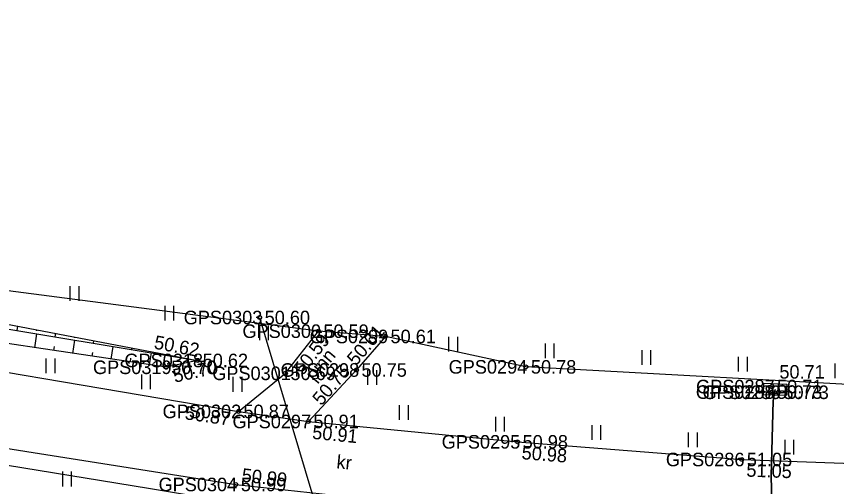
# Model space of a CAD drawing. Extents: x 551623 to 559850, y 6561220 to 6567135.
# Drawn here: x 555747.99 to 555790.35, y 6565368.67 to 6565392.98 of the extents above; entities that cross this region are included whole.
import ezdxf

# ---------------------------------------------------------------- set-up
doc = ezdxf.new("R2010")
doc.units = 0
for name, color, linetype in [('ELRAJATISMP', 7, 'Continuous'), ('HALJASTUS', 7, 'Continuous'), ('KORGUS-EH2000', 7, 'Continuous'), ('KPOHULIIN', 7, 'Continuous'), ('MOOTKORG-EH2000', 7, 'Continuous'), ('MOOTMPUNKT', 7, 'Continuous'), ('MOOTNR', 7, 'Continuous'), ('MOOTPIIR', 7, 'Continuous'), ('MPKAABEL', 7, 'Continuous'), ('RELJEEF', 7, 'Continuous'), ('TEE', 7, 'Continuous')]:
    doc.layers.add(name, color=color, linetype=linetype)

msp = doc.modelspace()

# ---------------------------------------------------------------- linework, layer by layer
at = {"layer": 'ELRAJATISMP'}
for p, q in [((555787.054, 6565373.996), (555787.035, 6565373.4)), ((555787.325, 6565373.988), (555787.306, 6565373.391))]:
    msp.add_line(p, q, dxfattribs=at)
msp.add_lwpolyline([(555786.593, 6565374.011), (555787.787, 6565373.973), (555787.768, 6565373.376), (555786.574, 6565373.414)], close=True, dxfattribs=at)
at = {"layer": 'HALJASTUS'}
for p, q in [((555750.751, 6565379.034), (555750.751, 6565378.273)), ((555751.206, 6565379.034), (555751.206, 6565378.273)), ((555755.647, 6565378.018), (555755.647, 6565377.257)), ((555756.102, 6565378.018), (555756.102, 6565377.257)), ((555760.542, 6565377.003), (555760.542, 6565376.242)), ((555760.997, 6565377.003), (555760.997, 6565376.242)), ((555770.307, 6565376.408), (555770.307, 6565375.647)), ((555770.762, 6565376.408), (555770.762, 6565375.647)), ((555775.296, 6565376.065), (555775.296, 6565375.304)), ((555775.751, 6565376.065), (555775.751, 6565375.304)), ((555780.284, 6565375.722), (555780.284, 6565374.961)), ((555780.739, 6565375.722), (555780.739, 6565374.961)), ((555749.513, 6565375.294), (555749.513, 6565374.532)), ((555749.968, 6565375.294), (555749.968, 6565374.532)), ((555785.272, 6565375.379), (555785.272, 6565374.618)), ((555785.727, 6565375.379), (555785.727, 6565374.618)), ((555790.26, 6565375.036), (555790.26, 6565374.275)), ((555754.443, 6565374.461), (555754.443, 6565373.699)), ((555754.898, 6565374.461), (555754.898, 6565373.699)), ((555759.172, 6565374.338), (555759.172, 6565373.577)), ((555759.627, 6565374.338), (555759.627, 6565373.577)), ((555766.128, 6565374.695), (555766.128, 6565373.933)), ((555766.583, 6565374.695), (555766.583, 6565373.933)), ((555767.761, 6565372.88), (555767.761, 6565372.119)), ((555768.217, 6565372.88), (555768.217, 6565372.119)), ((555772.725, 6565372.277), (555772.725, 6565371.516)), ((555773.18, 6565372.277), (555773.18, 6565371.516)), ((555777.706, 6565371.85), (555777.706, 6565371.089)), ((555778.161, 6565371.85), (555778.161, 6565371.089)), ((555782.691, 6565371.472), (555782.691, 6565370.711)), ((555783.147, 6565371.472), (555783.147, 6565370.711)), ((555787.677, 6565371.093), (555787.677, 6565370.332)), ((555788.132, 6565371.093), (555788.132, 6565370.332)), ((555750.365, 6565369.444), (555750.365, 6565368.683)), ((555750.82, 6565369.444), (555750.82, 6565368.683))]:
    msp.add_line(p, q, dxfattribs=at)
at = {"layer": 'KORGUS-EH2000'}
for centre in [(555760.551, 6565377.411), (555763.583, 6565376.705), (555767.052, 6565376.433), (555757.349, 6565375.192), (555755.723, 6565374.838), (555765.551, 6565374.698), (555774.303, 6565374.86), (555787.015, 6565373.841), (555759.458, 6565372.557), (555763.069, 6565372.038), (555773.873, 6565370.985), (555785.453, 6565370.072), (555759.321, 6565368.781)]:
    msp.add_circle(centre, 0.1, dxfattribs=at)
at = {"layer": 'KPOHULIIN'}
msp.add_lwpolyline([(555760.551, 6565377.411), (555766.29, 6565358.132), (555768.381, 6565350.27)], dxfattribs=at)
at = {"layer": 'MOOTMPUNKT'}
for centre in [(555760.551, 6565377.411), (555763.583, 6565376.705), (555767.052, 6565376.433), (555757.349, 6565375.192), (555755.723, 6565374.838), (555765.551, 6565374.698), (555774.303, 6565374.86), (555761.883, 6565374.526), (555787.015, 6565373.841), (555787.001, 6565373.557), (555787.345, 6565373.546), (555759.458, 6565372.557), (555763.069, 6565372.038), (555773.873, 6565370.985), (555785.453, 6565370.072), (555759.321, 6565368.781)]:
    msp.add_circle(centre, 0.1, dxfattribs=at)
at = {"layer": 'MOOTPIIR'}
msp.add_lwpolyline([(555870.644, 6565361.764), (555852.219, 6565361.421), (555851.243, 6565363.431), (555851.072, 6565365.834), (555850.919, 6565369.424), (555850.689, 6565372.676), (555824.92, 6565373.681), (555819.298, 6565374.346), (555817.733, 6565372.559), (555794.391, 6565373.752), (555774.303, 6565374.86), (555767.052, 6565376.433), (555763.583, 6565376.705), (555741.853, 6565379.526), (555720.243, 6565384.972), (555695.628, 6565390.499), (555681.099, 6565394.714), (555669.53, 6565398.005), (555662.804, 6565398.822)], dxfattribs=at)
at = {"layer": 'MPKAABEL'}
for points in [[(555774.476, 6565357.809), (555773.987, 6565358.656), (555773.548, 6565362.88), (555772.65, 6565365.396), (555772.969, 6565366.239), (555776.199, 6565366.008), (555781.754, 6565365.504), (555786.281, 6565365.398), (555786.776, 6565365.686), (555787.003, 6565367.798), (555786.966, 6565369.233), (555787.074, 6565373.096), (555787.18, 6565373.694)], [(555787.18, 6565373.694), (555787.074, 6565373.096), (555786.966, 6565369.233), (555787.003, 6565367.798), (555786.776, 6565365.686), (555786.281, 6565365.398), (555781.754, 6565365.504), (555776.199, 6565366.008), (555772.969, 6565366.239)], [(555774.496, 6565357.816), (555774, 6565357.484), (555773.691, 6565358.398), (555773.449, 6565359.738), (555773.359, 6565361.879), (555773.121, 6565362.922), (555772.641, 6565364.68), (555771.98, 6565365.648), (555770.672, 6565366.172), (555763.27, 6565367.16), (555754.809, 6565368.578), (555745.82, 6565370.031)]]:
    msp.add_lwpolyline(points, dxfattribs=at)
at = {"layer": 'RELJEEF'}
for p, q in [((555748.048, 6565376.97), (555748.004, 6565376.74)), ((555748.933, 6565375.85), (555749.04, 6565376.568)), ((555749.03, 6565376.782), (555749.018, 6565376.72)), ((555750.012, 6565376.594), (555749.978, 6565376.413)), ((555750.911, 6565375.555), (555751.013, 6565376.242)), ((555750.995, 6565376.407), (555750.986, 6565376.36)), ((555751.977, 6565376.219), (555751.951, 6565376.086)), ((555752.959, 6565376.031), (555752.953, 6565375.999)), ((555749.922, 6565375.703), (555749.953, 6565375.913)), ((555751.9, 6565375.408), (555751.93, 6565375.609)), ((555752.889, 6565375.26), (555752.986, 6565375.915)), ((555753.941, 6565375.844), (555753.925, 6565375.759)), ((555754.867, 6565374.965), (555754.96, 6565375.588)), ((555754.923, 6565375.656), (555754.92, 6565375.638)), ((555753.878, 6565375.113), (555753.906, 6565375.304)), ((555755.906, 6565375.468), (555755.899, 6565375.432)), ((555756.831, 6565375.079), (555756.787, 6565375.285)), ((555756.888, 6565375.28), (555756.887, 6565375.277)), ((555755.854, 6565374.866), (555755.815, 6565375.045))]:
    msp.add_line(p, q, dxfattribs=at)
for points in [[(555695.628, 6565390.499), (555695.052, 6565388.937), (555720.222, 6565382.979), (555741.364, 6565378.247), (555757.349, 6565375.192), (555755.723, 6565374.838), (555741.151, 6565377.01), (555719.315, 6565381.302), (555694.718, 6565386.873), (555691.907, 6565387.524), (555678.96, 6565390.023), (555670.827, 6565391.88), (555670.328, 6565392.887)], [(555694.565, 6565390.891), (555694.035, 6565388.383), (555719.805, 6565382.57), (555741.241, 6565377.86), (555757.349, 6565375.192)]]:
    msp.add_lwpolyline(points, dxfattribs=at)
at = {"layer": 'TEE'}
for points in [[(555463.469, 6565434.873), (555479.318, 6565431.962), (555490.115, 6565429.76), (555497.95, 6565427.828), (555519.263, 6565422.564), (555542.613, 6565417.073), (555565.599, 6565412.035), (555589.51, 6565406.357), (555610.656, 6565401.422), (555635.154, 6565395.619), (555656.789, 6565389.809), (555677.01, 6565385.399), (555692.063, 6565381.655), (555718.607, 6565376.133), (555737.61, 6565372.216), (555759.321, 6565368.781), (555773.34, 6565367.27), (555785.196, 6565366.246), (555799.302, 6565365.674), (555824.141, 6565365.476), (555838.654, 6565365.624), (555851.072, 6565365.834)], [(555669.53, 6565398.005), (555669.393, 6565393.924), (555669.794, 6565392.158), (555670.453, 6565390.974), (555678.315, 6565388.964), (555693.278, 6565385.81), (555719.15, 6565380.087), (555738.319, 6565376.143), (555759.458, 6565372.557), (555763.069, 6565372.038), (555773.873, 6565370.985), (555785.453, 6565370.072), (555799.764, 6565369.552), (555819.003, 6565369.583), (555821.106, 6565370.429), (555821.559, 6565371.986), (555822.022, 6565373.687)], [(555759.458, 6565372.557), (555761.883, 6565374.526), (555763.583, 6565376.705)], [(555767.052, 6565376.433), (555765.551, 6565374.698), (555763.069, 6565372.038)]]:
    msp.add_lwpolyline(points, dxfattribs=at)

# ---------------------------------------------------------------- texts
at = {"layer": 'KORGUS-EH2000'}
for s, p in [(' 50.60', (555760.551, 6565377.061)), (' 50.78', (555774.303, 6565374.51)), (' 50.71', (555787.135, 6565374.252))]:
    msp.add_text(s, height=0.7, dxfattribs=at).set_placement(p)
for s, rotation, p in [(' 50.61', 49.1273, (555765.354, 6565374.682)), (' 50.62', 349.1795, (555754.803, 6565375.86)), (' 50.59', 52.0419, (555762.623, 6565374.176)), (' 50.70', 12.2991, (555755.91, 6565373.983)), (' 50.75', 49.1273, (555763.569, 6565372.619)), (' 50.87', 351.8253, (555756.402, 6565372.191)), (' 50.91', 354.4321, (555762.984, 6565371.167)), (' 50.98', 355.4925, (555773.804, 6565370.113)), (' 51.05', 357.9166, (555785.421, 6565369.198)), (' 50.99', 353.849, (555759.34, 6565368.955))]:
    msp.add_text(s, height=0.7, rotation=rotation, dxfattribs=at).set_placement(p)
at = {"layer": 'MOOTKORG-EH2000'}
for s, p in [(' 50.60', (555760.551, 6565377.061)), (' 50.59', (555763.583, 6565376.355)), (' 50.61', (555767.052, 6565376.083)), (' 50.70', (555755.723, 6565374.488)), (' 50.62', (555757.349, 6565374.842)), (' 50.78', (555774.303, 6565374.51)), (' 50.69', (555761.883, 6565374.176)), (' 50.75', (555765.551, 6565374.348)), (' 50.73', (555787.001, 6565373.207)), (' 50.71', (555787.015, 6565373.491)), (' 50.73', (555787.345, 6565373.196)), (' 50.87', (555759.458, 6565372.207)), (' 50.91', (555763.069, 6565371.688)), (' 50.98', (555773.873, 6565370.635)), (' 51.05', (555785.453, 6565369.722)), (' 50.99', (555759.321, 6565368.431))]:
    msp.add_text(s, height=0.7, dxfattribs=at).set_placement(p)
at = {"layer": 'MOOTNR'}
for s, p in [('GPS0303 ', (555756.631, 6565377.061)), ('GPS0300 ', (555759.663, 6565376.355)), ('GPS0299 ', (555763.132, 6565376.083)), ('GPS0319 ', (555751.944, 6565374.488)), ('GPS0318 ', (555753.57, 6565374.842)), ('GPS0294 ', (555770.313, 6565374.51)), ('GPS0301 ', (555758.104, 6565374.176)), ('GPS0298 ', (555761.631, 6565374.348)), ('GPS0288 ', (555783.081, 6565373.207)), ('GPS0287 ', (555783.095, 6565373.491)), ('GPS0289 ', (555783.425, 6565373.196)), ('GPS0302 ', (555755.539, 6565372.207)), ('GPS0297 ', (555759.15, 6565371.688)), ('GPS0295 ', (555769.953, 6565370.635)), ('GPS0286 ', (555781.533, 6565369.722)), ('GPS0304 ', (555755.331, 6565368.431))]:
    msp.add_text(s, height=0.7, dxfattribs=at).set_placement(p)
at = {"layer": 'TEE'}
for s, rotation, p in [('pinn', 50.1118, (555763.39, 6565374.069)), ('kr', 354.5617, (555764.499, 6565369.617))]:
    msp.add_text(s, height=0.7, rotation=rotation, dxfattribs=at).set_placement(p)

doc.saveas('drawing.dxf')
